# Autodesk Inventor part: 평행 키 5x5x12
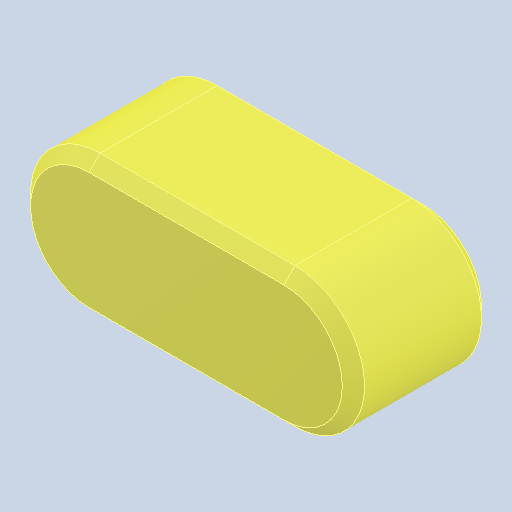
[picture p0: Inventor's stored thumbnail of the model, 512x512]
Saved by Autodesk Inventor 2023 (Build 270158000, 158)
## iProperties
Created: 2025-03
Part Number: 평행 키 5x5x12
Material: 강철, 연강
Description: 키 및 해당 키홈
Document SubType Name: Modeling
Designer: user
Density: 7.85 g/cm^3
Appearance: 기본값
Author: jhkim
Sending System: Autodesk Inventor 2025
Preprocessor: ST-DEVELOPER v20
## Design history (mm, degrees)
feature "Solid1"
node "솔리드1"
